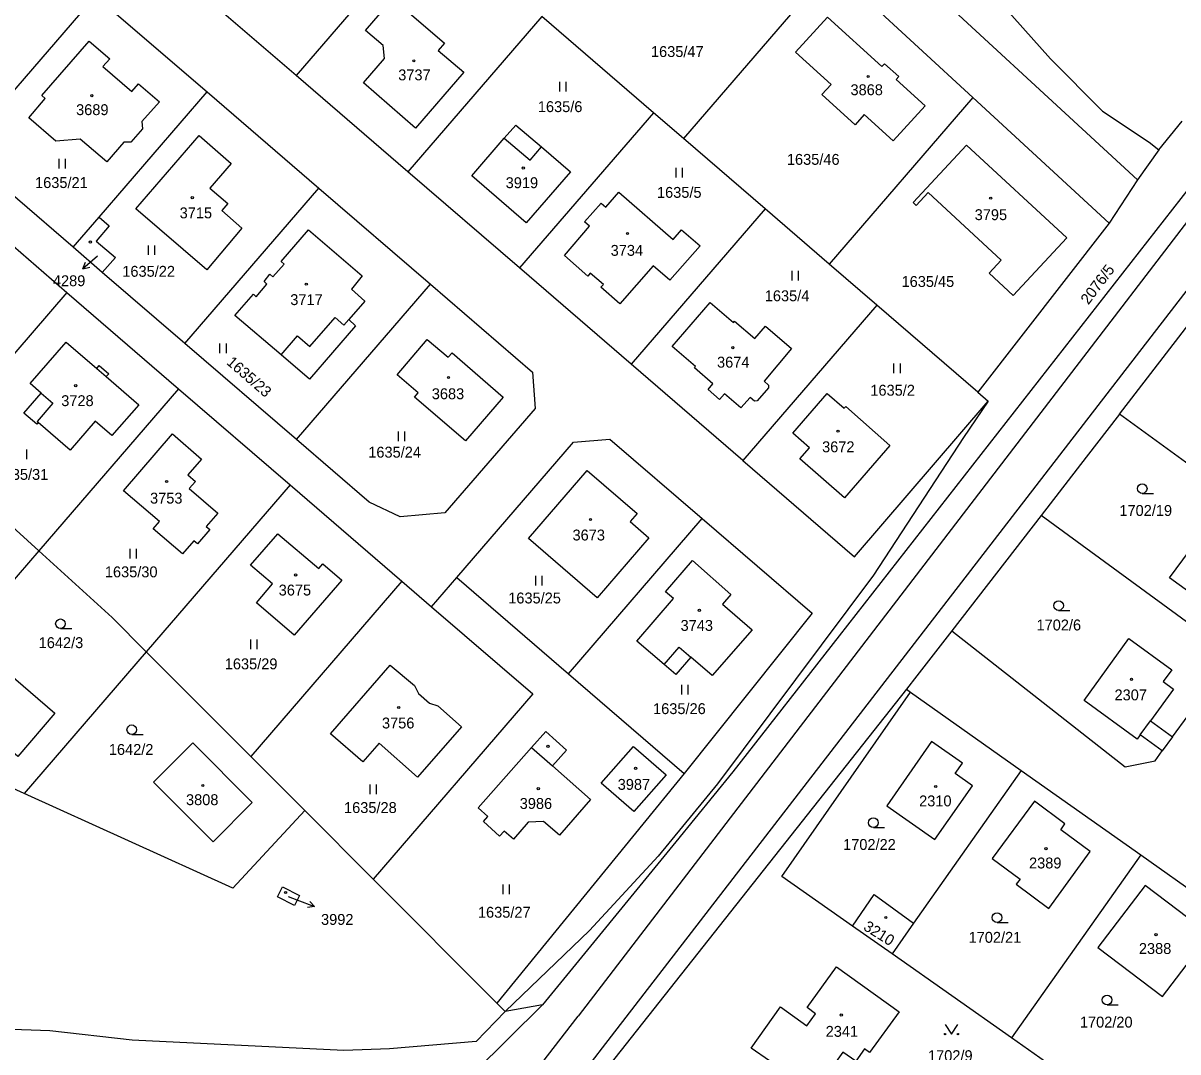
# Model space of a CAD drawing. Extents: x -679220 to -673243, y -1075091 to -1066557.
# Drawn here: x -677199.8 to -677019.6, y -1071935.7 to -1071775.1 of the extents above; entities that cross this region are included whole.
import ezdxf

# ---------------------------------------------------------------- set-up
doc = ezdxf.new("R2010")
doc.units = 0
for name, color, linetype in [('Hranice parcel', 7, 'Continuous'), ('Parcelní čísla', 7, 'Continuous'), ('Pop  PČ popisy', 7, 'Continuous'), ('Vnitřní kresba', 7, 'Continuous'), ('Značky budov', 7, 'Continuous'), ('Značky kultur', 7, 'Continuous')]:
    doc.layers.add(name, color=color, linetype=linetype)

msp = doc.modelspace()

# ---------------------------------------------------------------- linework, layer by layer
at = {"layer": 'Hranice parcel'}
for p, q in [((-677136.33, -1071759.08), (-677157.23, -1071783.32)), ((-677073.73, -1071766.37), (-677096.78, -1071793.16)), ((-677051.64, -1071786.74), (-677073.73, -1071766.37)), ((-677157.23, -1071783.32), (-677174.65, -1071768.31)), ((-677118.9, -1071774.1), (-677139.8, -1071798.34)), ((-677101.48, -1071789.11), (-677118.9, -1071774.1)), ((-677139.8, -1071798.34), (-677157.23, -1071783.32)), ((-677187.94, -1071805.41), (-677171.11, -1071785.87)), ((-677171.11, -1071785.87), (-677153.69, -1071800.88)), ((-677051.64, -1071786.74), (-677074.06, -1071812.74)), ((-677030.37, -1071806.36), (-677051.64, -1071786.74)), ((-677101.48, -1071789.11), (-677122.38, -1071813.35)), ((-677096.78, -1071793.16), (-677101.48, -1071789.11)), ((-677022.61, -1071794.93), (-677018.95, -1071790.41)), ((-677084.05, -1071804.12), (-677096.78, -1071793.16)), ((-677022.61, -1071794.93), (-677025.94, -1071799.59)), ((-677122.38, -1071813.35), (-677139.8, -1071798.34)), ((-677025.94, -1071799.59), (-677030.37, -1071806.36)), ((-677174.58, -1071825.13), (-677153.69, -1071800.88)), ((-677153.69, -1071800.88), (-677136.26, -1071815.89)), ((-677210.42, -1071802.16), (-677193, -1071817.18)), ((-677192, -1071810.12), (-677187.94, -1071805.41)), ((-677187.94, -1071805.41), (-677186.38, -1071806.76)), ((-677084.05, -1071804.12), (-677104.95, -1071828.36)), ((-677074.06, -1071812.74), (-677084.05, -1071804.12)), ((-677030.37, -1071806.36), (-677050.86, -1071832.72)), ((-677187.46, -1071814.04), (-677192, -1071810.12)), ((-677185.41, -1071811.73), (-677187.46, -1071814.04)), ((-677174.58, -1071825.13), (-677187.46, -1071814.04)), ((-677104.95, -1071828.36), (-677122.38, -1071813.35)), ((-677066.63, -1071819.14), (-677074.06, -1071812.74)), ((-677157.15, -1071840.14), (-677136.26, -1071815.89)), ((-677193, -1071817.18), (-677214.53, -1071842.17)), ((-677193, -1071817.18), (-677175.58, -1071832.19)), ((-677066.63, -1071819.14), (-677087.53, -1071843.38)), ((-677050.86, -1071832.72), (-677066.63, -1071819.14)), ((-677028.76, -1071836.15), (-677016.51, -1071820.3)), ((-677157.15, -1071840.14), (-677174.58, -1071825.13)), ((-677087.53, -1071843.38), (-677104.95, -1071828.36)), ((-677175.58, -1071832.19), (-677197.38, -1071857.49)), ((-677175.58, -1071832.19), (-677158.15, -1071847.2)), ((-677050.86, -1071832.72), (-677049.21, -1071834.14)), ((-676999.37, -1071857.63), (-677028.76, -1071836.15)), ((-677158.15, -1071847.2), (-677180.6, -1071873.25)), ((-677158.15, -1071847.2), (-677140.73, -1071862.22)), ((-677040.99, -1071851.99), (-677054.9, -1071869.98)), ((-677011.17, -1071873.78), (-677040.99, -1071851.99)), ((-677114.73, -1071876.7), (-677093.84, -1071852.45)), ((-677197.38, -1071857.49), (-677219.88, -1071883.62)), ((-677140.73, -1071862.22), (-677164.3, -1071889.58)), ((-677140.73, -1071862.22), (-677136.07, -1071866.23)), ((-677136.07, -1071866.23), (-677132.15, -1071861.68)), ((-677132.15, -1071861.68), (-677114.73, -1071876.7)), ((-677180.6, -1071873.25), (-677199.67, -1071895.38)), ((-677180.6, -1071873.25), (-677164.3, -1071889.58)), ((-677020.49, -1071886.53), (-677011.17, -1071873.78)), ((-677114.73, -1071876.7), (-677096.66, -1071892.27)), ((-677061.99, -1071879.1), (-677061.35, -1071879.56)), ((-677061.35, -1071879.56), (-677044.1, -1071891.8)), ((-677020.49, -1071886.53), (-677022.08, -1071888.72)), ((-677164.3, -1071889.58), (-677155.88, -1071898.02)), ((-677044.1, -1071891.8), (-677060.87, -1071915.61)), ((-677044.1, -1071891.8), (-677025.4, -1071904.97)), ((-677096.66, -1071892.27), (-677125.89, -1071928.08)), ((-677145.18, -1071908.75), (-677155.88, -1071898.02)), ((-677025.4, -1071904.97), (-677045.61, -1071933.51)), ((-677025.4, -1071904.97), (-677006.52, -1071918.32)), ((-677125.89, -1071928.08), (-677145.18, -1071908.75)), ((-677064.23, -1071920.38), (-677070.39, -1071916.06)), ((-677060.87, -1071915.61), (-677064.23, -1071920.38)), ((-677045.61, -1071933.51), (-677064.23, -1071920.38)), ((-677124.61, -1071929.42), (-677125.89, -1071928.08)), ((-677118.79, -1071928.36), (-677124.61, -1071929.42)), ((-677035.24, -1071940.8), (-677045.61, -1071933.51))]:
    msp.add_line(p, q, dxfattribs=at)
for points in [[(-677203.81, -1071626.06), (-677205.28, -1071627.7), (-677204.89, -1071634.52), (-677143.42, -1071691.21), (-677025.94, -1071799.59)], [(-677078.77, -1071736.63), (-677039.53, -1071780.68), (-677031.38, -1071788.86), (-677024.1, -1071793.73), (-677022.61, -1071794.93)], [(-677192, -1071810.12), (-677209.43, -1071795.1), (-677188.54, -1071770.86), (-677171.11, -1071785.87)], [(-677138.57, -1071791.51), (-677146.72, -1071784.47), (-677143.45, -1071780.64), (-677143.66, -1071778.61), (-677146.38, -1071776.26), (-677142.13, -1071771.3), (-677134.08, -1071778.28), (-677135.04, -1071779.42), (-677131.04, -1071782.79), (-677138.57, -1071791.51)], [(-677074.33, -1071774.18), (-677065.81, -1071781.9), (-677065.41, -1071781.46), (-677063.18, -1071783.48), (-677063.59, -1071783.92), (-677059.07, -1071788.02), (-677064.04, -1071793.5), (-677068.56, -1071789.4), (-677070, -1071790.99), (-677075.19, -1071786.29), (-677073.74, -1071784.7), (-677079.3, -1071779.66), (-677074.33, -1071774.18)], [(-677182.84, -1071785.82), (-677181.81, -1071784.6), (-677178.55, -1071787.42), (-677181.27, -1071790.47), (-677181.18, -1071791.64), (-677182.99, -1071793.69), (-677184.11, -1071793.71), (-677186.78, -1071796.8), (-677190.91, -1071793.25), (-677194.72, -1071793.58), (-677198.93, -1071789.93), (-677196.36, -1071786.91), (-677196.88, -1071786.43), (-677189.5, -1071777.93), (-677186.28, -1071780.69), (-677187.38, -1071781.9), (-677182.84, -1071785.82)], [(-677008.25, -1071788.41), (-677013.98, -1071795.82), (-677072.5, -1071870.78), (-677089.07, -1071891.97), (-677097.96, -1071902.91), (-677118.79, -1071928.36)], [(-677118.92, -1071794.46), (-677114.42, -1071798.32), (-677121.31, -1071806.31), (-677129.8, -1071798.98), (-677124.75, -1071793.09), (-677122.93, -1071791.06), (-677118.92, -1071794.46)], [(-677168.81, -1071804.38), (-677165.67, -1071807.14), (-677171.17, -1071813.65), (-677182.22, -1071804.1), (-677172.36, -1071792.69), (-677167.37, -1071797.05), (-677170.66, -1071800.89), (-677167.88, -1071803.29), (-677168.81, -1071804.38)], [(-677047.22, -1071812.14), (-677058.6, -1071801.57), (-677060.47, -1071803.58), (-677060.96, -1071803.14), (-677052.61, -1071794.17), (-677036.95, -1071808.64), (-677045.32, -1071817.64), (-677049.09, -1071814.16), (-677047.22, -1071812.14)], [(-677112.2, -1071806.17), (-677109.62, -1071803.22), (-677108.89, -1071803.86), (-677106.85, -1071801.53), (-677098.4, -1071808.91), (-677097.1, -1071807.39), (-677094.19, -1071809.87), (-677098.89, -1071815.26), (-677101.53, -1071813), (-677106.72, -1071818.94), (-677109.65, -1071816.36), (-677109.26, -1071815.92), (-677111.32, -1071814.18), (-677111.7, -1071814.61), (-677115.36, -1071811.38), (-677111.46, -1071806.82), (-677112.2, -1071806.17)], [(-677186.38, -1071806.76), (-677188.43, -1071809.14), (-677185.41, -1071811.73)], [(-677155.3, -1071807.4), (-677146.9, -1071814.56), (-677148.59, -1071816.63), (-677146.5, -1071818.51), (-677148.98, -1071821.41), (-677147.93, -1071822.36), (-677155.15, -1071830.71), (-677159.57, -1071826.92), (-677166.8, -1071820.74), (-677163.88, -1071817.42), (-677163.45, -1071817.83), (-677161.78, -1071815.88), (-677162.22, -1071815.48), (-677161.33, -1071814.31), (-677160.84, -1071814.72), (-677159.09, -1071812.74), (-677159.54, -1071812.35), (-677155.3, -1071807.4)], [(-677136.26, -1071815.89), (-677120.36, -1071829.62), (-677119.94, -1071835.26), (-677133.99, -1071851.56), (-677140.98, -1071852.19), (-677145.84, -1071849.88), (-677157.15, -1071840.14)], [(-677094.89, -1071828.72), (-677098.54, -1071825.61), (-677092.61, -1071818.73), (-677088.96, -1071821.84), (-677088.8, -1071821.65), (-677085.66, -1071824.37), (-677083.96, -1071822.41), (-677079.9, -1071825.94), (-677084.2, -1071831.04), (-677083.53, -1071831.64), (-677083.53, -1071832.08), (-677085.27, -1071834.08), (-677085.68, -1071834.14), (-677086.38, -1071833.57), (-677087.82, -1071835.2), (-677090.38, -1071833.01), (-677091.16, -1071833.88), (-677092.95, -1071832.3), (-677092.18, -1071831.43), (-677095.07, -1071828.93), (-677094.89, -1071828.72)], [(-677181.74, -1071834.71), (-677185.96, -1071839.52), (-677188.6, -1071837.26), (-677192.5, -1071841.78), (-677197.48, -1071837.47), (-677197.68, -1071837.73), (-677199.69, -1071836.01), (-677196.99, -1071832.87), (-677198.71, -1071831.38), (-677193.11, -1071824.92), (-677188.33, -1071829.04), (-677187.94, -1071828.58), (-677186.46, -1071829.86), (-677186.85, -1071830.31), (-677181.74, -1071834.71)], [(-677136.76, -1071824.49), (-677133.48, -1071827.25), (-677132.88, -1071826.61), (-677124.91, -1071833.5), (-677130.77, -1071840.33), (-677138.75, -1071833.52), (-677138.17, -1071832.83), (-677141.44, -1071830.01), (-677136.76, -1071824.49)], [(-677049.21, -1071834.14), (-677053.08, -1071839.8), (-677067.12, -1071861.27), (-677091.47, -1071893.86), (-677100.71, -1071905.15), (-677111.46, -1071916.77), (-677124.61, -1071929.42)], [(-677087.53, -1071843.38), (-677070.09, -1071858.42), (-677049.21, -1071834.14)], [(-677074.35, -1071832.94), (-677071.71, -1071835.23), (-677071.47, -1071834.96), (-677064.56, -1071841.05), (-677071.63, -1071849.2), (-677078.61, -1071843.16), (-677077.11, -1071841.43), (-677079.73, -1071839.13), (-677074.35, -1071832.94)], [(-677028.76, -1071836.15), (-677033.96, -1071842.89), (-677040.99, -1071851.99)], [(-677171.27, -1071853.7), (-677170.7, -1071854.19), (-677172.6, -1071856.38), (-677173.18, -1071855.91), (-677174.96, -1071857.98), (-677179.52, -1071854.08), (-677178.55, -1071852.92), (-677184.13, -1071848.11), (-677176.5, -1071839.26), (-677171.97, -1071843.21), (-677174.09, -1071845.65), (-677172.94, -1071846.66), (-677173.9, -1071847.78), (-677169.46, -1071851.62), (-677171.27, -1071853.7)], [(-677132.15, -1071861.68), (-677113.94, -1071840.54), (-677108.27, -1071840.09), (-677093.84, -1071852.45)], [(-677214.53, -1071842.17), (-677207.43, -1071848.35), (-677197.38, -1071857.49)], [(-677102.18, -1071855.45), (-677110.24, -1071864.82), (-677120.95, -1071855.57), (-677111.78, -1071844.96), (-677104.02, -1071851.65), (-677105.12, -1071852.92), (-677102.18, -1071855.45)], [(-677005.22, -1071865.64), (-677008.7, -1071863.14), (-677012.24, -1071868.03), (-677020.96, -1071861.72), (-677013.66, -1071851.9), (-677005.88, -1071857.48), (-677007.18, -1071859.28), (-677006.34, -1071859.87), (-677007.17, -1071861.02), (-677003.69, -1071863.54)], [(-677093.84, -1071852.45), (-677076.7, -1071867.24), (-677096.66, -1071892.27)], [(-677163.39, -1071865.6), (-677160.93, -1071862.64), (-677164.33, -1071859.72), (-677160.06, -1071854.82), (-677153.67, -1071860.23), (-677153.05, -1071859.5), (-677150.07, -1071862.06), (-677157.51, -1071870.66), (-677163.39, -1071865.6)], [(-677197.38, -1071857.49), (-677185.94, -1071867.89), (-677180.6, -1071873.25)], [(-677104.06, -1071871.57), (-677098.34, -1071864.94), (-677099.59, -1071863.89), (-677095.39, -1071859.03), (-677089.37, -1071864.29), (-677090.7, -1071865.84), (-677086.04, -1071869.82), (-677092.32, -1071876.95), (-677095.65, -1071874.08), (-677097.97, -1071876.78), (-677099.77, -1071875.24), (-677104.06, -1071871.57)], [(-677136.07, -1071866.23), (-677120.27, -1071879.84), (-677145.18, -1071908.75)], [(-677054.9, -1071869.98), (-677060.35, -1071877.02), (-677061.99, -1071879.1)], [(-677054.9, -1071869.98), (-677027.87, -1071891.23), (-677023.2, -1071890.25), (-677022.08, -1071888.72)], [(-677202.37, -1071873.72), (-677203.66, -1071875.27), (-677194.85, -1071882.84), (-677200.63, -1071889.6), (-677209.63, -1071881.88), (-677209.06, -1071881.22), (-677211.47, -1071879.14), (-677204.92, -1071871.53), (-677202.37, -1071873.72)], [(-677022.08, -1071888.72), (-677025.5, -1071886.22), (-677025.98, -1071886.91), (-677034.25, -1071880.87), (-677027.27, -1071871.19), (-677020.58, -1071876.07), (-677021.93, -1071877.91), (-677020.31, -1071879.1), (-677023.9, -1071884.04), (-677020.49, -1071886.53)], [(-677142.57, -1071875.33), (-677138.75, -1071878.54), (-677138.12, -1071879.77), (-677136.39, -1071881.26), (-677135.11, -1071881.71), (-677131.39, -1071884.96), (-677138.26, -1071892.8), (-677144.28, -1071887.53), (-677146.81, -1071890.43), (-677151.86, -1071886.06), (-677142.57, -1071875.33)], [(-677061.99, -1071879.1), (-677110.05, -1071939.9), (-677113.06, -1071943.65)], [(-677070.39, -1071916.06), (-677081.41, -1071908.33), (-677061.35, -1071879.56)], [(-677199.67, -1071895.38), (-677210.59, -1071890.43), (-677219.88, -1071883.62)], [(-677111.28, -1071896.31), (-677116.12, -1071901.87), (-677118.6, -1071899.75), (-677121, -1071899.85), (-677123.32, -1071902.5), (-677124.78, -1071901.26), (-677125.5, -1071902.02), (-677128, -1071899.76), (-677127.28, -1071898.95), (-677128.8, -1071897.59), (-677120.48, -1071888.21), (-677118.25, -1071885.7), (-677115.05, -1071888.62), (-677117.19, -1071891.07), (-677111.28, -1071896.31)], [(-677170.18, -1071902.93), (-677179.47, -1071893.6), (-677173.36, -1071887.47), (-677164.09, -1071896.8), (-677170.18, -1071902.93)], [(-677099.49, -1071892.47), (-677104.5, -1071898.16), (-677109.62, -1071893.74), (-677104.59, -1071888.03), (-677099.49, -1071892.47)], [(-677051.68, -1071894.16), (-677054.38, -1071892.26), (-677053.25, -1071890.66), (-677058.07, -1071887.28), (-677065.07, -1071897.28), (-677057.57, -1071902.55), (-677051.68, -1071894.16)], [(-677155.88, -1071898.02), (-677167.07, -1071910.13), (-677199.67, -1071895.38)], [(-677037.9, -1071901.02), (-677037.29, -1071900.1), (-677042, -1071896.57), (-677048.6, -1071905.51), (-677044.26, -1071908.72), (-677044.86, -1071909.53), (-677039.76, -1071913.3), (-677033.31, -1071904.41), (-677037.9, -1071901.02)], [(-677160.11, -1071911.51), (-677159.33, -1071909.94), (-677156.67, -1071911.29), (-677157.45, -1071912.84), (-677160.11, -1071911.51)], [(-677014.64, -1071917.37), (-677024.73, -1071909.71), (-677032.1, -1071919.42), (-677022.01, -1071927.08), (-677014.64, -1071917.37)], [(-677070.39, -1071916.06), (-677067.01, -1071911.12), (-677060.87, -1071915.61)], [(-677124.61, -1071929.42), (-677129.15, -1071934.09), (-677142.65, -1071935.21), (-677149.77, -1071935.51), (-677182.8, -1071933.85), (-677195.63, -1071932.39), (-677219.15, -1071931.59), (-677230.48, -1071931.85), (-677242.62, -1071934.17), (-677249.52, -1071933.31), (-677281.62, -1071930.03), (-677298.71, -1071927.05), (-677361.97, -1071918.81)], [(-677083.37, -1071937.12), (-677086.19, -1071935.13), (-677081.63, -1071928.65), (-677077.51, -1071931.61), (-677076.16, -1071929.74), (-677077.5, -1071928.78), (-677072.9, -1071922.4), (-677063.13, -1071929.44), (-677067.73, -1071935.82), (-677068.53, -1071935.25), (-677069.9, -1071937.16), (-677071.9, -1071935.72), (-677076.28, -1071941.87)], [(-677138.12, -1071946.93), (-677131.91, -1071941.25), (-677129.41, -1071938.86), (-677118.79, -1071928.36)]]:
    msp.add_lwpolyline(points, dxfattribs=at)
at = {"layer": 'Pop  PČ popisy'}
for p, q in [((-677188.22, -1071811.53), (-677190.48, -1071813.5)), ((-677190.48, -1071813.5), (-677190.06, -1071812.46)), ((-677190.48, -1071813.5), (-677189.4, -1071813.22)), ((-677158.44, -1071911.46), (-677157.13, -1071911.96)), ((-677157.13, -1071911.96), (-677154.33, -1071913.03)), ((-677154.33, -1071913.03), (-677155.44, -1071913.14)), ((-677154.33, -1071913.03), (-677155.08, -1071912.21))]:
    msp.add_line(p, q, dxfattribs=at)
at = {"layer": 'Vnitřní kresba'}
for p, q in [((-676986.75, -1071775.9), (-677036.69, -1071840.72)), ((-677124.75, -1071793.09), (-677120.72, -1071796.54)), ((-677120.72, -1071796.54), (-677118.92, -1071794.46)), ((-677009.81, -1071795.15), (-677113.2, -1071930.1)), ((-677155.07, -1071825.61), (-677151.14, -1071821.06)), ((-677151.14, -1071821.06), (-677149.76, -1071822.29)), ((-677149.76, -1071822.29), (-677148.98, -1071821.41)), ((-677159.57, -1071826.92), (-677157, -1071823.95)), ((-677157, -1071823.95), (-677155.07, -1071825.61)), ((-677188.33, -1071829.04), (-677186.85, -1071830.31)), ((-677196.99, -1071832.87), (-677195.17, -1071834.46)), ((-677195.17, -1071834.46), (-677197.64, -1071837.33)), ((-677197.64, -1071837.33), (-677197.48, -1071837.47)), ((-677036.69, -1071840.72), (-677109.47, -1071935.07)), ((-677099.77, -1071875.24), (-677097.45, -1071872.54)), ((-677097.45, -1071872.54), (-677095.65, -1071874.08)), ((-677025.5, -1071886.22), (-677023.9, -1071884.04)), ((-677120.48, -1071888.21), (-677117.19, -1071891.07)), ((-677124.89, -1071945.24), (-677113.2, -1071930.1)), ((-677109.47, -1071935.07), (-677182.2, -1072029.42))]:
    msp.add_line(p, q, dxfattribs=at)
at = {"layer": 'Značky budov'}
for centre in [(-677138.85, -1071781.01), (-677067.96, -1071783.46), (-677189.09, -1071786.46), (-677121.77, -1071797.75), (-677173.42, -1071802.37), (-677048.84, -1071802.45), (-677105.51, -1071807.96), (-677189.32, -1071809.31), (-677155.63, -1071815.88), (-677089.08, -1071825.78), (-677133.44, -1071830.44), (-677191.61, -1071831.71), (-677072.65, -1071838.82), (-677177.42, -1071846.67), (-677111.28, -1071852.6), (-677157.29, -1071861.25), (-677094.29, -1071866.79), (-677026.87, -1071877.57), (-677141.2, -1071881.95), (-677117.92, -1071888), (-677104.24, -1071891.46), (-677171.78, -1071894.12), (-677119.44, -1071894.6), (-677057.41, -1071894.28), (-677040.22, -1071903.97), (-677158.87, -1071910.83), (-677065.2, -1071914.72), (-677023.03, -1071917.4), (-677072.16, -1071929.96)]:
    msp.add_circle(centre, 0.175, dxfattribs=at)
at = {"layer": 'Značky kultur'}
for p, q in [((-677116.08, -1071785.78), (-677116.08, -1071784.28)), ((-677115.08, -1071785.78), (-677115.08, -1071784.28)), ((-677194.19, -1071797.8), (-677194.19, -1071796.3)), ((-677193.19, -1071797.8), (-677193.19, -1071796.3)), ((-677097.91, -1071799.23), (-677097.91, -1071797.73)), ((-677096.91, -1071799.23), (-677096.91, -1071797.73)), ((-677180.25, -1071811.32), (-677180.25, -1071809.82)), ((-677179.25, -1071811.32), (-677179.25, -1071809.82)), ((-677079.83, -1071815.31), (-677079.83, -1071813.81)), ((-677078.83, -1071815.31), (-677078.83, -1071813.81)), ((-677169.1, -1071826.62), (-677169.1, -1071825.12)), ((-677168.1, -1071826.62), (-677168.1, -1071825.12)), ((-677063.94, -1071829.76), (-677063.94, -1071828.26)), ((-677062.94, -1071829.76), (-677062.94, -1071828.26)), ((-677141.24, -1071840.36), (-677141.24, -1071838.86)), ((-677140.24, -1071840.36), (-677140.24, -1071838.86)), ((-677199.24, -1071843.18), (-677199.24, -1071841.68)), ((-677025.2, -1071848.53), (-677023.45, -1071848.53)), ((-677183.12, -1071858.68), (-677183.12, -1071857.18)), ((-677182.12, -1071858.68), (-677182.12, -1071857.18)), ((-677119.81, -1071862.92), (-677119.81, -1071861.42)), ((-677118.81, -1071862.92), (-677118.81, -1071861.42)), ((-677038.25, -1071866.79), (-677036.5, -1071866.79)), ((-677193.99, -1071869.63), (-677192.24, -1071869.63)), ((-677164.28, -1071872.85), (-677164.28, -1071871.35)), ((-677163.28, -1071872.85), (-677163.28, -1071871.35)), ((-677097.03, -1071879.93), (-677097.03, -1071878.43)), ((-677096.03, -1071879.93), (-677096.03, -1071878.43)), ((-677182.86, -1071886.17), (-677181.11, -1071886.17)), ((-677145.67, -1071895.48), (-677145.67, -1071893.98)), ((-677144.67, -1071895.48), (-677144.67, -1071893.98)), ((-677067.15, -1071900.68), (-677065.4, -1071900.68)), ((-677124.93, -1071911.1), (-677124.93, -1071909.6)), ((-677123.93, -1071911.1), (-677123.93, -1071909.6)), ((-677047.85, -1071915.49), (-677046.1, -1071915.49)), ((-677030.68, -1071928.35), (-677028.93, -1071928.35))]:
    msp.add_line(p, q, dxfattribs=at)
msp.add_lwpolyline([(-677055.96, -1071931.42), (-677054.96, -1071932.92), (-677053.96, -1071931.42)], dxfattribs=at)
for centre, radius in [((-677025.2, -1071847.78), 0.75), ((-677038.25, -1071866.04), 0.75), ((-677193.99, -1071868.88), 0.75), ((-677182.86, -1071885.42), 0.75), ((-677067.15, -1071899.93), 0.75), ((-677047.85, -1071914.74), 0.75), ((-677030.68, -1071927.6), 0.75), ((-677055.96, -1071932.92), 0.1), ((-677053.96, -1071932.92), 0.1)]:
    msp.add_circle(centre, radius, dxfattribs=at)

# ---------------------------------------------------------------- texts
at = {"layer": 'Parcelní čísla'}
for s, p in [('1635/47', (-677101.85, -1071780.42)), ('3737', (-677141.29, -1071784.06)), ('3868', (-677070.72, -1071786.38)), ('1635/6', (-677119.5, -1071789.02)), ('3689', (-677191.55, -1071789.49)), ('1635/46', (-677080.64, -1071797.25)), ('1635/21', (-677197.95, -1071800.87)), ('3919', (-677124.52, -1071800.89)), ('1635/5', (-677100.91, -1071802.4)), ('3715', (-677175.39, -1071805.6)), ('3795', (-677051.34, -1071805.88)), ('3734', (-677108.14, -1071811.45)), ('4289', (-677195.17, -1071816.19)), ('1635/22', (-677184.34, -1071814.72)), ('1635/45', (-677062.75, -1071816.31)), ('3717', (-677158.13, -1071819.14)), ('1635/4', (-677084.09, -1071818.54)), ('3674', (-677091.54, -1071828.9)), ('3683', (-677136.05, -1071833.83)), ('1635/2', (-677067.62, -1071833.28)), ('3728', (-677193.87, -1071834.91)), ('1635/24', (-677145.96, -1071842.95)), ('3672', (-677075.15, -1071842.11)), ('1635/31', (-677204.11, -1071846.42)), ('3753', (-677180.01, -1071850.12)), ('1702/19', (-677028.76, -1071852.05)), ('3673', (-677114.09, -1071855.88)), ('1635/30', (-677187.06, -1071861.63)), ('3675', (-677159.94, -1071864.47)), ('1635/25', (-677124.12, -1071865.71)), ('3743', (-677097.23, -1071869.99)), ('1702/6', (-677041.69, -1071869.92)), ('1642/3', (-677197.39, -1071872.68)), ('1635/29', (-677168.35, -1071875.99)), ('2307', (-677029.52, -1071880.83)), ('1635/26', (-677101.52, -1071882.98)), ('3756', (-677143.82, -1071885.22)), ('1642/2', (-677186.44, -1071889.35)), ('3987', (-677107.04, -1071894.8)), ('3808', (-677174.4, -1071897.19)), ('1635/28', (-677149.74, -1071898.42)), ('3986', (-677122.33, -1071897.78)), ('2310', (-677060.01, -1071897.38)), ('1702/22', (-677071.87, -1071904.18)), ('2389', (-677042.86, -1071907.07)), ('1635/27', (-677128.85, -1071914.76)), ('3992', (-677153.33, -1071915.88)), ('1702/21', (-677052.29, -1071918.67)), ('2388', (-677025.72, -1071920.42)), ('2341', (-677074.59, -1071933.35)), ('1702/20', (-677034.92, -1071931.9)), ('1702/9', (-677058.62, -1071937.14))]:
    msp.add_text(s, height=1.7, dxfattribs=at).set_placement(p)
for s, rotation, p in [('2076/5', 53, (-677033.6, -1071819.18)), ('1635/23', 319, (-677168.2, -1071828.26)), ('3210', 328, (-677068.84, -1071916.56))]:
    msp.add_text(s, height=1.7, rotation=rotation, dxfattribs=at).set_placement(p)

doc.saveas('drawing.dxf')
